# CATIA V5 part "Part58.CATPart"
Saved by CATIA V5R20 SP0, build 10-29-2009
Part number: 9FA 042212
Revision: ANY
Definition: UNKNOWN
Nomenclature: 9FA 042212
Source: Unknown
Bounding box of the stored display mesh (mm): x -2 to 2, y 0.1 to 12.1, z -2 to 2
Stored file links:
  C:\Users\Utente\Desktop\IO LAVORO\3D X SITO CF\CUMSA\3D files FA\FA 042212-20\Part58.CATPart

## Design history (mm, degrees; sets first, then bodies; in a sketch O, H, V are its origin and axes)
Set1 "FacciaKO#NONE#9186"
  DatumSurface1 "Sup9186_1"
  DatumCurve1 "Crv9186_1"
Body1 "Cortar-Extruir3" (main body)
  Solid1: solid without history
